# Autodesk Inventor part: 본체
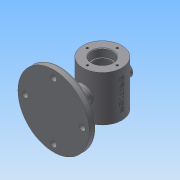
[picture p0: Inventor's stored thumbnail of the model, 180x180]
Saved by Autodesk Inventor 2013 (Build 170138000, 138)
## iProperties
Created: 2018-12
Part Number: 본체
Material: 일반
Document SubType Name: Modeling
Designer: Administrator
Density: 1 g/cm^3
Author: Administrator
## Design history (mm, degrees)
sketch "스케치2"
  geometry: C1 r 30 at (0, 0); 1 further point
  constraints: 1 centre point, 1 coincident
  dimensions: "d22" = 60 diameter of C1
extrude "돌출2" new body sketch "스케치2" stored distance "d23" = 70; taper "d24" = 0 deg
hole "구멍3" diameter "d27" = 32; stored, may be unused: countersink angle "d31" = 90 deg, drill point angle "d33" = 0 deg; dims "d25" = 10, "d26" = 10, "d28" = 6, "d29" = 4, "d30" = 2, "d32" = 12
hole "구멍4" diameter "d36" = 28; stored, may be unused: countersink angle "d40" = 90 deg, drill point angle "d42" = 0 deg; dims "d34" = 10, "d35" = 10, "d37" = 6, "d38" = 4, "d39" = 2, "d41" = 3
hole "구멍5" diameter "d45" = 50; stored, may be unused: countersink angle "d49" = 90 deg, drill point angle "d51" = 0 deg; dims "d43" = 10, "d44" = 10, "d46" = 6, "d47" = 4, "d48" = 2, "d50" = 40
node "작업 평면1"
sketch "스케치3"
  geometry: C1 r 55 at (0, 0); 1 further point
  constraints: 1 centre point, 1 coincident
  dimensions: "d53" = 110 diameter of C1
extrude "돌출3" join sketch "스케치3" distance "d54" = 10; taper "d55" = 0 deg
sketch "스케치4"
  geometry: L1 (-65, -55)-(-65, 55) reference; L2 (-65, -55)-(-65, 55) reference; L3 (-75, 55)-(-75, -55) reference; L4 (-65, -55)-(-53.478, -12); L5 (-65, 0)-(-53.478, 0); L6 (-53.478, -12)-(-53.478, 0); L7 (-65, 0)-(-65, -55); 1 further point
  constraints: 8 end point, 2 coincident, 2 perpendicular, 1 midpoint
  dimensions: "d56" = 43 vertical distance of L4.start L4.end; "d58" = 165 deg angle of L4 L6
revolve "회전1" sketch "스케치4" stored, may be unused: angle "d59" = 90 deg
sketch "스케치5"
  geometry: C1 r 55 at (0, 0) reference; C2 r 12 at (0, 0) reference; C3 r 12 at (0, 0)
  constraints: 1 centre point, 1 coincident
  dimensions: "d60" = 24 diameter of C3
extrude "돌출4" join sketch "스케치5" stored distance "d61" = 10; taper "d62" = 0 deg
node "작업 평면2"
sketch "스케치6"
  geometry: C1 r 10 at (0, 0); 1 further point
  constraints: 1 centre point, 1 coincident
  dimensions: "d64" = 20 diameter of C1
extrude "돌출5" join sketch "스케치6" stored distance "d65" = 10; taper "d66" = 0 deg
hole "구멍6" diameter "d69" = 10; stored, may be unused: countersink angle "d73" = 90 deg, drill point angle "d75" = 0 deg; dims "d67" = 10, "d68" = 10, "d70" = 6, "d71" = 4, "d72" = 2, "d74" = 40
sketch "스케치7"
  geometry: 1 further point
hole "구멍7" sketch "스케치7" at (0, 44) diameter "d77" = 9; stored, may be unused: countersink angle "d81" = 90 deg, drill point angle "d83" = 0 deg; dims "d78" = 6, "d79" = 4, "d80" = 2, "d82" = 10
hole "구멍8" diameter "d86" = 14; stored, may be unused: countersink angle "d90" = 90 deg, drill point angle "d92" = 0 deg; dims "d84" = 10, "d85" = 10, "d87" = 6, "d88" = 4, "d89" = 2, "d91" = 10
sketch "스케치8"
  geometry: 1 further point
hole "구멍9" sketch "스케치8" at (0, 23) diameter "d97" = 3.242; stored, may be unused: countersink angle "d101" = 90 deg, drill point angle "d103" = 118 deg; dims "d98" = 8, "d99" = 4, "d100" = 2, "d102" = 10
node "작업 평면3"
sketch "스케치9"
  geometry: L1 (30, 35)-(-30, 35) reference; L2 (30, -35)-(30, 35) reference; 2 further points
  constraints: 1 other
  dimensions: "d108" = 35 distance from line of L1 point (0, 0); "d109" = 30 distance from line of L2 point (0, 0)
feature "엠보싱1" sketch "스케치9" dims "d54" = 10, "d55" = 0, "d110" = 0.5, "d111" = 0
fillet "모깎기1" dims "d112" = 3
fillet "모깎기2" dims "d113" = 0.3
chamfer "모따기1" distance "d114" = 1; stored, may be unused: second distance "d115" = 2, angle "d116" = 45 deg
chamfer "모따기2" distance "d117" = 1; stored, may be unused: second distance "d118" = 2, angle "d119" = 45 deg
node "솔리드2"
mirror "대칭1"
pattern_circular "원형 패턴1" dims angle "d94" = 360 deg
pattern_circular "원형 패턴2" dims angle "d105" = 360 deg
mirror "대칭2"
node "투영된 루프1"
node "투영된 루프2"
other parameters: "d52" = -75, "d63" = 37, "d107" = 34.5
